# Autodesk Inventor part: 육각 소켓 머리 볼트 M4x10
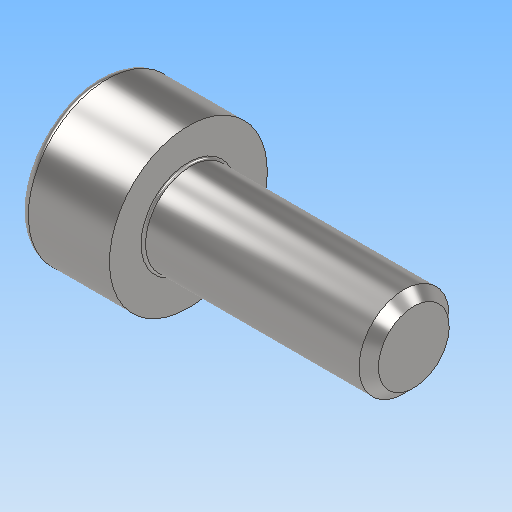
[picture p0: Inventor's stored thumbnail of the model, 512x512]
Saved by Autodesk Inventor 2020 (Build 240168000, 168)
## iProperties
Created: 2024-09
Part Number: 육각 소켓 머리 볼트 M4x10
Material: 강철, 연강
Description: 6각머리 태핑 나사
Document SubType Name: Modeling
Designer: oem
Density: 7.85 g/cm^3
Appearance: 기본값
Author: jhkim
Sending System: Autodesk Inventor 2025
Preprocessor: ST-DEVELOPER v20
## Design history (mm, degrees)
feature "Solid1"
node "솔리드1"
